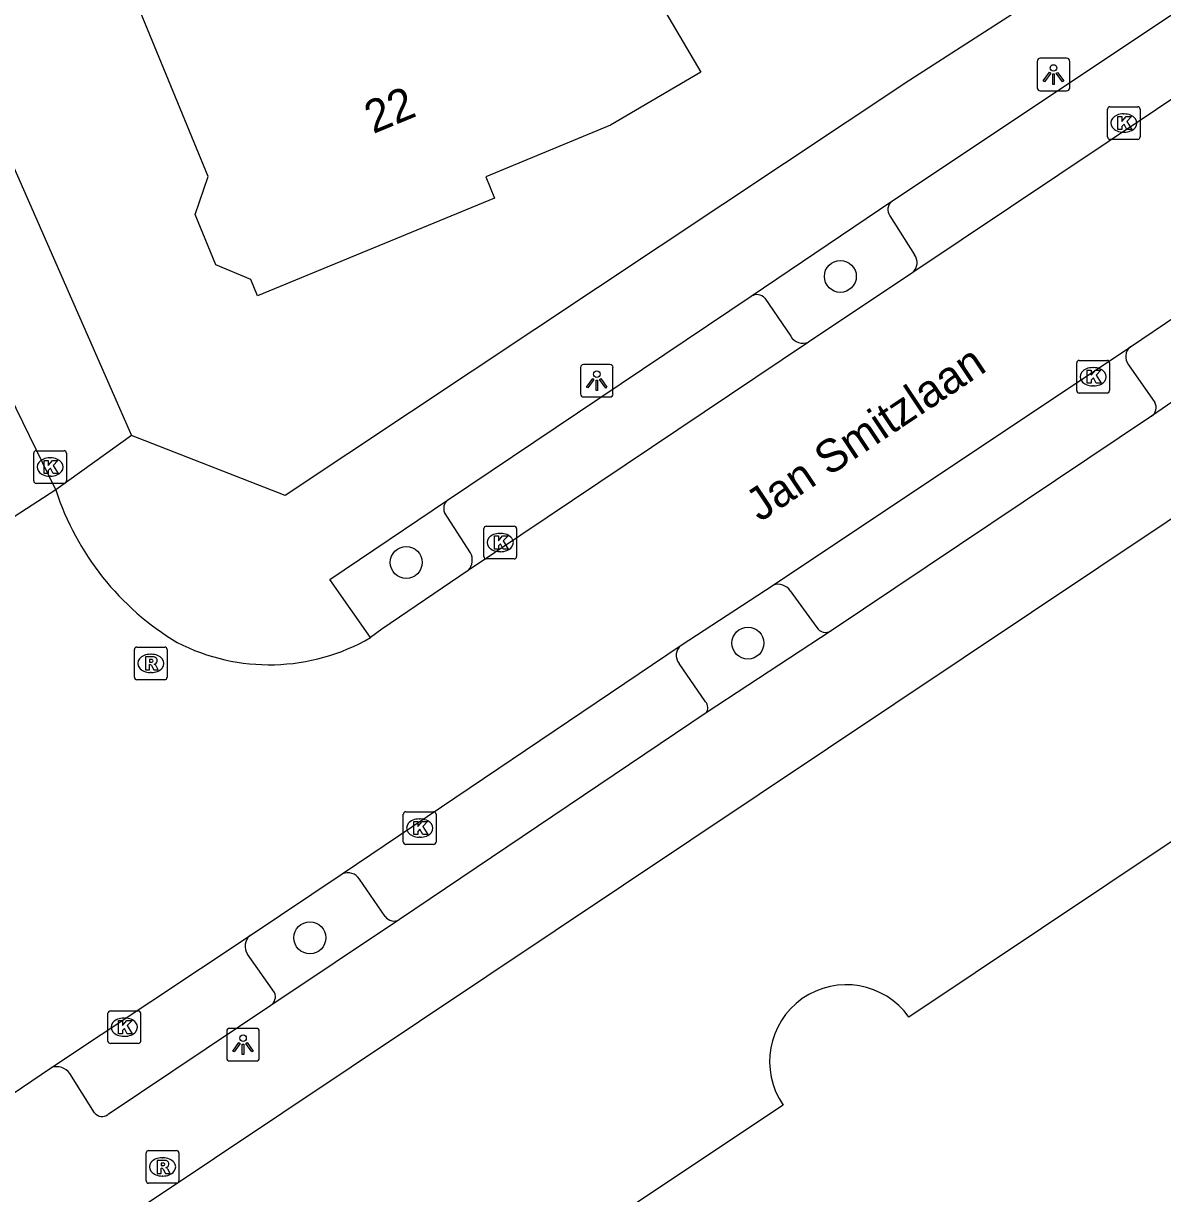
# Model space of a CAD drawing. Extents: x 161354 to 161876, y 382161 to 382804.
# Drawn here: x 161440.13 to 161474.99, y 382506.54 to 382542.36 of the extents above; entities that cross this region are included whole.
import ezdxf

# ---------------------------------------------------------------- set-up
doc = ezdxf.new("R2010")
doc.units = 0
for name, color, linetype in [('IMGEO_Boom', 7, 'Continuous'), ('IMGEO_Kolk', 7, 'Continuous'), ('IMGEO_Lichtpunt', 7, 'Continuous'), ('IMGEO_Openbare_ruimte_label', 7, 'Continuous'), ('IMGEO_Pand', 7, 'Continuous'), ('IMGEO_Pand_nummerreeks', 7, 'Continuous'), ('IMGEO_Parkeervlak_open', 7, 'Continuous'), ('IMGEO_Rijbaan_lokaal_open', 7, 'Continuous'), ('IMGEO_Rioolput', 7, 'Continuous'), ('IMGEO_Voetpad_open', 7, 'Continuous')]:
    doc.layers.add(name, color=color, linetype=linetype)

msp = doc.modelspace()

# ---------------------------------------------------------------- linework, layer by layer
at = {"layer": 'IMGEO_Boom'}
for centre in [(161465.131, 382534.614), (161451.848, 382525.858), (161462.303, 382523.389), (161448.899, 382514.368)]:
    msp.add_circle(centre, 0.489, dxfattribs=at)
at = {"layer": 'IMGEO_Kolk'}
for p, q in [((161473.305, 382538.882), (161473.305, 382539.734)), ((161473.38, 382539.808), (161474.232, 382539.808)), ((161473.793, 382539.588), (161473.818, 382539.588)), ((161474.306, 382539.734), (161474.306, 382538.882)), ((161474.232, 382538.808), (161473.38, 382538.808)), ((161473.816, 382539.028), (161473.791, 382539.028)), ((161472.365, 382531.116), (161472.365, 382531.968)), ((161472.44, 382532.042), (161473.292, 382532.042)), ((161473.366, 382531.968), (161473.366, 382531.116)), ((161472.853, 382531.822), (161472.878, 382531.822)), ((161472.876, 382531.262), (161472.851, 382531.262)), ((161473.292, 382531.042), (161472.44, 382531.042)), ((161440.449, 382528.353), (161440.449, 382529.205)), ((161440.524, 382529.279), (161441.376, 382529.279)), ((161441.45, 382529.205), (161441.45, 382528.353)), ((161440.937, 382529.059), (161440.962, 382529.059)), ((161440.96, 382528.499), (161440.935, 382528.499)), ((161441.376, 382528.279), (161440.524, 382528.279)), ((161454.298, 382526.967), (161455.15, 382526.967)), ((161454.223, 382526.041), (161454.223, 382526.893)), ((161454.711, 382526.747), (161454.736, 382526.747)), ((161455.224, 382526.893), (161455.224, 382526.041)), ((161455.15, 382525.967), (161454.298, 382525.967)), ((161454.734, 382526.187), (161454.709, 382526.187)), ((161451.758, 382517.299), (161451.758, 382518.151)), ((161451.833, 382518.225), (161452.685, 382518.225)), ((161452.246, 382518.005), (161452.271, 382518.005)), ((161452.759, 382518.151), (161452.759, 382517.299)), ((161452.269, 382517.445), (161452.244, 382517.445)), ((161452.685, 382517.225), (161451.833, 382517.225)), ((161442.719, 382511.205), (161442.719, 382512.057)), ((161442.794, 382512.131), (161443.646, 382512.131)), ((161443.207, 382511.911), (161443.232, 382511.911)), ((161443.72, 382512.057), (161443.72, 382511.205)), ((161443.23, 382511.351), (161443.205, 382511.351)), ((161443.646, 382511.131), (161442.794, 382511.131))]:
    msp.add_line(p, q, dxfattribs=at)
for points in [[(161473.305, 382538.882), (161473.305, 382539.734)], [(161473.38, 382539.808), (161474.232, 382539.808)], [(161473.626, 382539.508), (161473.749, 382539.508), (161473.749, 382539.357), (161473.879, 382539.508), (161474.043, 382539.508), (161473.897, 382539.357), (161474.05, 382539.108), (161473.898, 382539.108), (161473.813, 382539.272), (161473.749, 382539.205), (161473.749, 382539.108), (161473.626, 382539.108), (161473.626, 382539.508)], [(161474.306, 382539.734), (161474.306, 382538.882)], [(161474.232, 382538.808), (161473.38, 382538.808)], [(161472.365, 382531.116), (161472.365, 382531.968)], [(161472.44, 382532.042), (161473.292, 382532.042)], [(161473.366, 382531.968), (161473.366, 382531.116)], [(161472.686, 382531.742), (161472.809, 382531.742), (161472.809, 382531.591), (161472.939, 382531.742), (161473.103, 382531.742), (161472.957, 382531.591), (161473.11, 382531.342), (161472.958, 382531.342), (161472.873, 382531.506), (161472.809, 382531.439), (161472.809, 382531.342), (161472.686, 382531.342), (161472.686, 382531.742)], [(161473.292, 382531.042), (161472.44, 382531.042)], [(161440.449, 382528.353), (161440.449, 382529.205)], [(161440.524, 382529.279), (161441.376, 382529.279)], [(161441.45, 382529.205), (161441.45, 382528.353)], [(161440.77, 382528.979), (161440.893, 382528.979), (161440.893, 382528.828), (161441.023, 382528.979), (161441.187, 382528.979), (161441.041, 382528.828), (161441.194, 382528.579), (161441.042, 382528.579), (161440.957, 382528.743), (161440.893, 382528.676), (161440.893, 382528.579), (161440.77, 382528.579), (161440.77, 382528.979)], [(161441.376, 382528.279), (161440.524, 382528.279)], [(161454.298, 382526.967), (161455.15, 382526.967)], [(161454.223, 382526.041), (161454.223, 382526.893)], [(161454.544, 382526.667), (161454.667, 382526.667), (161454.667, 382526.516), (161454.797, 382526.667), (161454.961, 382526.667), (161454.815, 382526.516), (161454.968, 382526.267), (161454.816, 382526.267), (161454.731, 382526.431), (161454.667, 382526.364), (161454.667, 382526.267), (161454.544, 382526.267), (161454.544, 382526.667)], [(161455.224, 382526.893), (161455.224, 382526.041)], [(161455.15, 382525.967), (161454.298, 382525.967)], [(161451.758, 382517.299), (161451.758, 382518.151)], [(161451.833, 382518.225), (161452.685, 382518.225)], [(161452.759, 382518.151), (161452.759, 382517.299)], [(161452.079, 382517.925), (161452.202, 382517.925), (161452.202, 382517.774), (161452.332, 382517.925), (161452.496, 382517.925), (161452.35, 382517.774), (161452.503, 382517.525), (161452.351, 382517.525), (161452.266, 382517.689), (161452.202, 382517.622), (161452.202, 382517.525), (161452.079, 382517.525), (161452.079, 382517.925)], [(161452.685, 382517.225), (161451.833, 382517.225)], [(161442.719, 382511.205), (161442.719, 382512.057)], [(161442.794, 382512.131), (161443.646, 382512.131)], [(161443.72, 382512.057), (161443.72, 382511.205)], [(161443.04, 382511.831), (161443.163, 382511.831), (161443.163, 382511.68), (161443.293, 382511.831), (161443.457, 382511.831), (161443.311, 382511.68), (161443.464, 382511.431), (161443.312, 382511.431), (161443.227, 382511.595), (161443.163, 382511.528), (161443.163, 382511.431), (161443.04, 382511.431), (161443.04, 382511.831)], [(161443.646, 382511.131), (161442.794, 382511.131)]]:
    msp.add_lwpolyline(points, dxfattribs=at)
for centre, start, end in [((161473.382, 382539.732), 91.552, 178.448), ((161473.382, 382539.732), 91.552, 178.448), ((161474.23, 382539.732), 1.552, 88.448), ((161474.23, 382539.732), 1.552, 88.448), ((161473.382, 382538.884), 181.552, 268.448), ((161473.382, 382538.884), 181.552, 268.448), ((161474.23, 382538.884), 271.552, 358.448), ((161474.23, 382538.884), 271.552, 358.448), ((161472.442, 382531.966), 91.552, 178.448), ((161472.442, 382531.966), 91.552, 178.448), ((161473.29, 382531.966), 1.552, 88.448), ((161473.29, 382531.966), 1.552, 88.448), ((161472.442, 382531.118), 181.552, 268.448), ((161472.442, 382531.118), 181.552, 268.448), ((161473.29, 382531.118), 271.552, 358.448), ((161473.29, 382531.118), 271.552, 358.448), ((161440.526, 382529.203), 91.552, 178.448), ((161440.526, 382529.203), 91.552, 178.448), ((161441.374, 382529.203), 1.552, 88.448), ((161441.374, 382529.203), 1.552, 88.448), ((161440.526, 382528.355), 181.552, 268.448), ((161440.526, 382528.355), 181.552, 268.448), ((161441.374, 382528.355), 271.552, 358.448), ((161441.374, 382528.355), 271.552, 358.448), ((161454.3, 382526.891), 91.552, 178.448), ((161454.3, 382526.891), 91.552, 178.448), ((161455.148, 382526.891), 1.552, 88.448), ((161455.148, 382526.891), 1.552, 88.448), ((161454.3, 382526.043), 181.552, 268.448), ((161454.3, 382526.043), 181.552, 268.448), ((161455.148, 382526.043), 271.552, 358.448), ((161455.148, 382526.043), 271.552, 358.448), ((161451.835, 382518.149), 91.552, 178.448), ((161451.835, 382518.149), 91.552, 178.448), ((161452.683, 382518.149), 1.552, 88.448), ((161452.683, 382518.149), 1.552, 88.448), ((161451.835, 382517.301), 181.552, 268.448), ((161451.835, 382517.301), 181.552, 268.448), ((161452.683, 382517.301), 271.552, 358.448), ((161452.683, 382517.301), 271.552, 358.448), ((161442.796, 382512.055), 91.552, 178.448), ((161442.796, 382512.055), 91.552, 178.448), ((161443.644, 382512.055), 1.552, 88.448), ((161443.644, 382512.055), 1.552, 88.448), ((161442.796, 382511.207), 181.552, 268.448), ((161442.796, 382511.207), 181.552, 268.448), ((161443.644, 382511.207), 271.552, 358.448), ((161443.644, 382511.207), 271.552, 358.448)]:
    msp.add_arc(centre, 0.0765, start, end, dxfattribs=at)
for centre, major_axis, ratio, start_param, end_param in [((161473.792, 382539.308), (-0.387, 0.002), 0.722429, 4.712389, 7.853982), ((161473.817, 382539.308), (-0.39, 0.002), 0.717154, 1.570796, 4.712389), ((161472.852, 382531.542), (-0.387, 0.002), 0.722429, 4.712389, 7.853982), ((161472.877, 382531.542), (-0.39, 0.002), 0.717154, 1.570796, 4.712389), ((161440.936, 382528.779), (-0.387, 0.002), 0.722429, 4.712389, 7.853982), ((161440.961, 382528.779), (-0.39, 0.002), 0.717154, 1.570796, 4.712389), ((161454.71, 382526.467), (-0.387, 0.002), 0.722429, 4.712389, 7.853982), ((161454.735, 382526.467), (-0.39, 0.002), 0.717154, 1.570796, 4.712389), ((161452.245, 382517.725), (-0.387, 0.002), 0.722429, 4.712389, 7.853982), ((161452.27, 382517.725), (-0.39, 0.002), 0.717154, 1.570796, 4.712389), ((161443.206, 382511.631), (-0.387, 0.002), 0.722429, 4.712389, 7.853982), ((161443.231, 382511.631), (-0.39, 0.002), 0.717154, 1.570796, 4.712389)]:
    msp.add_ellipse(centre, major_axis=major_axis, ratio=ratio, start_param=start_param, end_param=end_param, dxfattribs=at)
at = {"layer": 'IMGEO_Lichtpunt'}
for p, q in [((161472.056, 382541.292), (161471.248, 382541.292)), ((161472.056, 382541.292), (161471.248, 382541.292)), ((161471.154, 382541.197), (161471.154, 382540.39)), ((161471.154, 382541.197), (161471.154, 382540.39)), ((161472.15, 382540.39), (161472.15, 382541.197)), ((161472.15, 382540.39), (161472.15, 382541.197)), ((161471.248, 382540.296), (161472.056, 382540.296)), ((161471.248, 382540.296), (161472.056, 382540.296)), ((161457.178, 382531.824), (161457.178, 382531.017)), ((161457.178, 382531.824), (161457.178, 382531.017)), ((161458.08, 382531.919), (161457.272, 382531.919)), ((161458.08, 382531.919), (161457.272, 382531.919)), ((161458.174, 382531.017), (161458.174, 382531.824)), ((161458.174, 382531.017), (161458.174, 382531.824)), ((161457.272, 382530.923), (161458.08, 382530.923)), ((161457.272, 382530.923), (161458.08, 382530.923)), ((161447.257, 382511.594), (161446.449, 382511.594)), ((161447.257, 382511.594), (161446.449, 382511.594)), ((161446.355, 382511.499), (161446.355, 382510.692)), ((161446.355, 382511.499), (161446.355, 382510.692)), ((161447.351, 382510.692), (161447.351, 382511.499)), ((161447.351, 382510.692), (161447.351, 382511.499)), ((161446.449, 382510.598), (161447.257, 382510.598)), ((161446.449, 382510.598), (161447.257, 382510.598))]:
    msp.add_line(p, q, dxfattribs=at)
for points in [[(161471.528, 382540.861), (161471.567, 382540.833), (161471.379, 382540.571), (161471.341, 382540.598), (161471.528, 382540.861)], [(161471.63, 382540.813), (161471.677, 382540.813), (161471.677, 382540.491), (161471.63, 382540.491), (161471.63, 382540.813)], [(161471.74, 382540.833), (161471.778, 382540.86), (161471.965, 382540.598), (161471.926, 382540.57), (161471.74, 382540.833)], [(161457.552, 382531.488), (161457.591, 382531.46), (161457.403, 382531.198), (161457.365, 382531.225), (161457.552, 382531.488)], [(161457.654, 382531.44), (161457.701, 382531.44), (161457.701, 382531.118), (161457.654, 382531.118), (161457.654, 382531.44)], [(161457.764, 382531.46), (161457.802, 382531.487), (161457.989, 382531.225), (161457.95, 382531.197), (161457.764, 382531.46)], [(161446.729, 382511.163), (161446.768, 382511.135), (161446.58, 382510.873), (161446.542, 382510.9), (161446.729, 382511.163)], [(161446.831, 382511.115), (161446.878, 382511.115), (161446.878, 382510.793), (161446.831, 382510.793), (161446.831, 382511.115)], [(161446.941, 382511.135), (161446.979, 382511.162), (161447.166, 382510.9), (161447.127, 382510.872), (161446.941, 382511.135)]]:
    msp.add_lwpolyline(points, dxfattribs=at)
for centre in [(161471.653, 382540.995), (161457.677, 382531.622), (161446.854, 382511.297)]:
    msp.add_circle(centre, 0.0994, dxfattribs=at)
for centre, start, end in [((161471.248, 382541.197), 90, 180), ((161471.248, 382541.197), 90, 180), ((161472.056, 382541.197), 0, 90), ((161472.056, 382541.197), 0, 90), ((161471.248, 382540.39), 180, 270), ((161471.248, 382540.39), 180, 270), ((161472.056, 382540.39), 270, 0), ((161472.056, 382540.39), 270, 360), ((161457.272, 382531.824), 90, 180), ((161457.272, 382531.824), 90, 180), ((161458.08, 382531.824), 0, 90), ((161458.08, 382531.824), 0, 90), ((161457.272, 382531.017), 180, 270), ((161457.272, 382531.017), 180, 270), ((161458.08, 382531.017), 270, 0), ((161458.08, 382531.017), 270, 360), ((161446.449, 382511.499), 90, 180), ((161446.449, 382511.499), 90, 180), ((161447.257, 382511.499), 0, 90), ((161447.257, 382511.499), 0, 90), ((161446.449, 382510.692), 180, 270), ((161446.449, 382510.692), 180, 270), ((161447.257, 382510.692), 270, 0), ((161447.257, 382510.692), 270, 360)]:
    msp.add_arc(centre, 0.0946, start, end, dxfattribs=at)
at = {"layer": 'IMGEO_Pand'}
for points in [[(161461.04, 382549.164), (161461.547, 382548.357), (161462.085, 382547.151), (161458.131, 382545.519), (161458.333, 382545.174), (161460.862, 382540.861), (161458.101, 382539.241), (161454.28, 382537.665), (161454.55, 382537.01), (161447.294, 382534.017), (161447.087, 382534.518), (161446.021, 382534.97), (161445.388, 382536.507), (161445.785, 382537.675), (161443.568, 382543.051)], [(161484.102, 382517.494), (161481.471, 382521.459), (161467.229, 382511.942)], [(161463.38, 382509.249), (161449.506, 382500), (161449.044, 382499.691), (161455.008, 382490.746)]]:
    msp.add_lwpolyline(points, dxfattribs=at)
msp.add_arc((161465.314, 382510.581), 2.349, 35.4002, 214.5578, dxfattribs=at)
at = {"layer": 'IMGEO_Parkeervlak_open'}
for points in [[(161466.648, 382536.471), (161467.399, 382535.277)], [(161462.823, 382533.949), (161463.614, 382532.78)], [(161473.949, 382531.907), (161474.756, 382530.757)], [(161453.813, 382526.156), (161453.018, 382527.388)], [(161463.599, 382524.986), (161464.409, 382523.863)], [(161461, 382521.592), (161460.194, 382522.766)], [(161451.204, 382515.02), (161450.416, 382516.165)], [(161447.819, 382512.693), (161446.987, 382513.864)]]:
    msp.add_lwpolyline(points, dxfattribs=at)
for centre, radius, start, end in [((161466.902, 382536.663), 0.318, 126.9067, 217.013), ((161467.08, 382535.036), 0.4, 311.6625, 37.1265), ((161462.58, 382533.73), 0.327, 42.0318, 122.1314), ((161463.988, 382533), 0.434, 210.4174, 292.5857), ((161474.258, 382532.156), 0.397, 129.5716, 218.905), ((161474.467, 382530.602), 0.328, 305.4324, 28.1623), ((161453.311, 382527.515), 0.319, 128.9656, 203.4658), ((161453.399, 382525.934), 0.47, 317.0557, 28.2261), ((161463.225, 382524.741), 0.447, 33.2495, 109.6183), ((161464.679, 382524.036), 0.321, 212.6332, 302.0061), ((161460.499, 382523.013), 0.392, 128.2719, 218.9797), ((161460.82, 382521.41), 0.256, 321.4173, 45.2764), ((161450.055, 382515.923), 0.435, 33.8493, 112.3736), ((161451.471, 382515.203), 0.324, 214.4605, 301.0977), ((161447.347, 382514.106), 0.433, 129.3403, 213.8993), ((161447.515, 382512.568), 0.329, 304.9239, 22.2655)]:
    msp.add_arc(centre, radius, start, end, dxfattribs=at)
at = {"layer": 'IMGEO_Rijbaan_lokaal_open'}
for points in [[(161441.122, 382528.078), (161437.877, 382534.716), (161434.209, 382543.084), (161431.634, 382549.918), (161430.022, 382554.586), (161429.794, 382555.37)], [(161477.789, 382541.723), (161467.346, 382534.737)], [(161467.346, 382534.737), (161464.155, 382532.599)], [(161474.005, 382532.462), (161476.85, 382534.371)], [(161464.155, 382532.599), (161453.743, 382525.614)], [(161463.075, 382525.162), (161474.005, 382532.462)], [(161441.122, 382528.078), (161436.736, 382525.241)], [(161453.743, 382525.614), (161451.1, 382523.811), (161450.753, 382523.557)], [(161460.256, 382523.321), (161463.075, 382525.162)], [(161449.889, 382516.325), (161460.256, 382523.321)], [(161447.072, 382514.441), (161449.889, 382516.325)], [(161440.996, 382510.396), (161447.072, 382514.441)], [(161436.707, 382507.496), (161440.996, 382510.396)]]:
    msp.add_lwpolyline(points, dxfattribs=at)
for centre, radius, start, end in [((161449.212, 382530.703), 8.505, 197.979, 239.0527), ((161447.66, 382528.903), 6.177, 242.8154, 300.0512)]:
    msp.add_arc(centre, radius, start, end, dxfattribs=at)
at = {"layer": 'IMGEO_Rioolput'}
for p, q in [((161443.529, 382522.341), (161443.529, 382523.193)), ((161443.604, 382523.267), (161444.456, 382523.267)), ((161444.017, 382523.047), (161444.042, 382523.047)), ((161444.53, 382523.193), (161444.53, 382522.341)), ((161444.04, 382522.487), (161444.015, 382522.487)), ((161444.456, 382522.267), (161443.604, 382522.267)), ((161443.89, 382506.928), (161443.89, 382507.78)), ((161443.965, 382507.854), (161444.817, 382507.854)), ((161444.378, 382507.634), (161444.403, 382507.634)), ((161444.891, 382507.78), (161444.891, 382506.928)), ((161444.401, 382507.074), (161444.376, 382507.074)), ((161444.817, 382506.854), (161443.965, 382506.854))]:
    msp.add_line(p, q, dxfattribs=at)
for points in [[(161443.529, 382522.341), (161443.529, 382523.193)], [(161443.604, 382523.267), (161444.456, 382523.267)], [(161444.53, 382523.193), (161444.53, 382522.341)], [(161444.118, 382522.965), (161443.866, 382522.967), (161443.866, 382522.567)], [(161443.866, 382522.567), (161443.99, 382522.567), (161443.99, 382522.729), (161444.001, 382522.729)], [(161444.044, 382522.886), (161443.99, 382522.886), (161443.99, 382522.805)], [(161443.99, 382522.805), (161444.042, 382522.805)], [(161444.048, 382522.7), (161444.119, 382522.567), (161444.259, 382522.567), (161444.194, 382522.693)], [(161444.456, 382522.267), (161443.604, 382522.267)], [(161443.89, 382506.928), (161443.89, 382507.78)], [(161443.965, 382507.854), (161444.817, 382507.854)], [(161444.891, 382507.78), (161444.891, 382506.928)], [(161444.479, 382507.552), (161444.227, 382507.554), (161444.227, 382507.154)], [(161444.227, 382507.154), (161444.351, 382507.154), (161444.351, 382507.316), (161444.362, 382507.316)], [(161444.405, 382507.473), (161444.351, 382507.473), (161444.351, 382507.392)], [(161444.351, 382507.392), (161444.403, 382507.392)], [(161444.409, 382507.287), (161444.48, 382507.154), (161444.62, 382507.154), (161444.555, 382507.28)], [(161444.817, 382506.854), (161443.965, 382506.854)]]:
    msp.add_lwpolyline(points, dxfattribs=at)
for centre, radius, start, end in [((161443.606, 382523.191), 0.0765, 91.552, 178.448), ((161443.606, 382523.191), 0.0765, 91.552, 178.448), ((161444.454, 382523.191), 0.0765, 1.552, 88.448), ((161444.454, 382523.191), 0.0765, 1.552, 88.448), ((161444, 382522.676), 0.0533, 26.0293, 88.6989), ((161444.026, 382522.994), 0.19, 274.7715, 282.9687), ((161444.05, 382522.79), 0.0964, 77.0061, 93.1865), ((161444.064, 382522.847), 0.0378, 276.6634, 79.6772), ((161444.117, 382522.855), 0.109, 350.3612, 89.416), ((161444.115, 382522.855), 0.112, 277.5842, 350.9817), ((161444.099, 382522.64), 0.108, 29.5134, 73.7905), ((161443.606, 382522.343), 0.0765, 181.552, 268.448), ((161443.606, 382522.343), 0.0765, 181.552, 268.448), ((161444.454, 382522.343), 0.0765, 271.552, 358.448), ((161444.454, 382522.343), 0.0765, 271.552, 358.448), ((161443.967, 382507.778), 0.0765, 91.552, 178.448), ((161443.967, 382507.778), 0.0765, 91.552, 178.448), ((161444.815, 382507.778), 0.0765, 1.552, 88.448), ((161444.815, 382507.778), 0.0765, 1.552, 88.448), ((161444.361, 382507.263), 0.0533, 26.0293, 88.6989), ((161444.387, 382507.581), 0.19, 274.7715, 282.9687), ((161444.411, 382507.377), 0.0964, 77.0061, 93.1865), ((161444.425, 382507.434), 0.0378, 276.6634, 79.6772), ((161444.478, 382507.442), 0.109, 350.3612, 89.416), ((161444.476, 382507.442), 0.112, 277.5842, 350.9817), ((161444.46, 382507.227), 0.108, 29.5134, 73.7905), ((161443.967, 382506.93), 0.0765, 181.552, 268.448), ((161443.967, 382506.93), 0.0765, 181.552, 268.448), ((161444.815, 382506.93), 0.0765, 271.552, 358.448), ((161444.815, 382506.93), 0.0765, 271.552, 358.448)]:
    msp.add_arc(centre, radius, start, end, dxfattribs=at)
for centre, major_axis, ratio, start_param, end_param in [((161444.016, 382522.767), (-0.387, 0.002), 0.722429, 4.712389, 7.853982), ((161444.041, 382522.767), (-0.39, 0.002), 0.717154, 1.570796, 4.712389), ((161444.377, 382507.354), (-0.387, 0.002), 0.722429, 4.712389, 7.853982), ((161444.402, 382507.354), (-0.39, 0.002), 0.717154, 1.570796, 4.712389)]:
    msp.add_ellipse(centre, major_axis=major_axis, ratio=ratio, start_param=start_param, end_param=end_param, dxfattribs=at)
at = {"layer": 'IMGEO_Voetpad_open'}
for points in [[(161459.276, 382654.164), (161449.465, 382654.844), (161447.977, 382652.326), (161442.636, 382642.916), (161437.607, 382632.685), (161435.473, 382627.706), (161432.284, 382616.838), (161429.648, 382602.151), (161428.735, 382591.734), (161428.36, 382584.865), (161428.803, 382579.556), (161430.088, 382568.58), (161430.881, 382563.561), (161434.555, 382551.436), (161439.58, 382538.533), (161443.443, 382529.747)], [(161505.762, 382577.804), (161506.699, 382576.294), (161504.018, 382564.655), (161500.558, 382562.342), (161483.051, 382550.779), (161467.26, 382540.62), (161448.144, 382527.905), (161443.443, 382529.747)], [(161435.571, 382500.672), (161489.707, 382536.855), (161494.481, 382540.047), (161497.103, 382541.796), (161500, 382543.743), (161509.001, 382549.792), (161508.958, 382549.917), (161512.013, 382551.566), (161524.1, 382548.864)], [(161466.711, 382536.917), (161476.027, 382543.146)], [(161462.406, 382534.007), (161466.711, 382536.917)], [(161453.11, 382527.763), (161462.406, 382534.007)], [(161478.472, 382532.953), (161474.657, 382530.335)], [(161474.657, 382530.335), (161464.849, 382523.764)], [(161443.443, 382529.747), (161441.122, 382528.078)], [(161450.753, 382523.557), (161449.513, 382525.333), (161453.11, 382527.763)], [(161464.849, 382523.764), (161461.02, 382521.25)], [(161461.02, 382521.25), (161451.638, 382514.926)], [(161451.638, 382514.926), (161447.703, 382512.299)], [(161447.703, 382512.299), (161442.721, 382508.954)], [(161442.311, 382509.012), (161441.548, 382510.213)]]:
    msp.add_lwpolyline(points, dxfattribs=at)
for centre, radius, start, end in [((161441.153, 382509.944), 0.478, 34.1866, 109.1304), ((161442.544, 382509.184), 0.29, 216.4418, 307.4545)]:
    msp.add_arc(centre, radius, start, end, dxfattribs=at)

# ---------------------------------------------------------------- texts
at = {"layer": 'IMGEO_Openbare_ruimte_label'}
msp.add_text('Jan Smitzlaan', height=1, rotation=33.706, dxfattribs=at).set_placement((161462.67, 382527.079))
at = {"layer": 'IMGEO_Pand_nummerreeks'}
msp.add_text('22', height=1, rotation=22.4141, dxfattribs=at).set_placement((161450.835, 382538.969))

doc.saveas('drawing.dxf')
